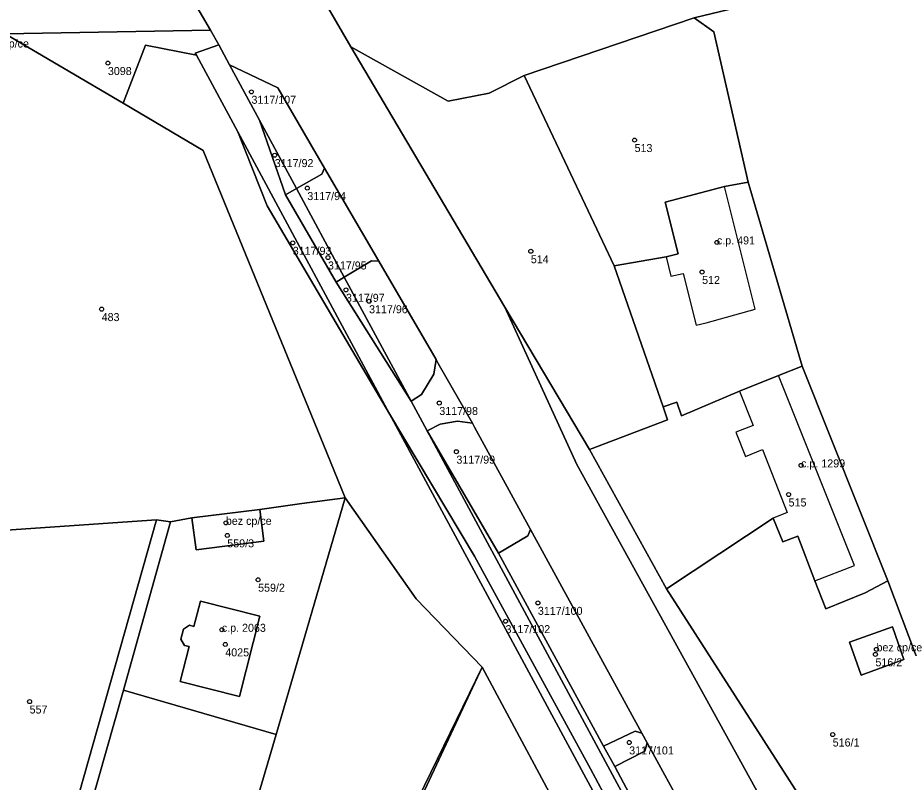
# Model space of a CAD drawing. Extents: x -878211 to -870363, y -1058464 to -1052522.
# Drawn here: x -874178.2 to -874067.3, y -1056521.1 to -1056425.6 of the extents above; entities that cross this region are included whole.
import ezdxf

# ---------------------------------------------------------------- set-up
doc = ezdxf.new("R2010")
doc.units = 0
for name, color, linetype in [('Definiční body', 7, 'Continuous'), ('Polygon budovy', 7, 'Continuous'), ('Polygon parcely', 7, 'Continuous')]:
    doc.layers.add(name, color=color, linetype=linetype)

msp = doc.modelspace()

# ---------------------------------------------------------------- linework, layer by layer
at = {"layer": 'Definiční body'}
for centre in [(-874166.98, -1056431.25994), (-874149.04, -1056434.84994), (-874101.17, -1056440.87994), (-874146.13, -1056442.75994), (-874142.06, -1056446.87994), (-874143.88, -1056453.71994), (-874090.88, -1056453.65994), (-874114.13, -1056454.76994), (-874139.48, -1056455.54994), (-874092.73, -1056457.35994), (-874137.23, -1056459.58994), (-874167.76, -1056461.99994), (-874134.34, -1056461.01994), (-874125.57, -1056473.72994), (-874123.43, -1056479.80994), (-874080.36, -1056481.51994), (-874081.92, -1056485.15994), (-874152.24, -1056488.69994), (-874152.06, -1056490.26994), (-874148.21, -1056495.80994), (-874113.25, -1056498.69994), (-874117.29, -1056500.98994), (-874152.74, -1056502.05994), (-874152.31, -1056503.88994), (-874071.07, -1056505.12994), (-874070.94, -1056504.49994), (-874176.76, -1056511.02994), (-874076.41, -1056515.14994), (-874101.84, -1056516.13994)]:
    msp.add_circle(centre, 0.25, dxfattribs=at)
at = {"layer": 'Polygon budovy'}
for points in [[(-874089.95, -1056446.66), (-874097.35, -1056448.64), (-874095.72, -1056455.08), (-874097.23, -1056455.46), (-874096.63, -1056457.89), (-874095.1, -1056457.53), (-874093.48, -1056464.01), (-874092.22, -1056463.71), (-874086.09, -1056462)], [(-874086.35, -1056476.52), (-874088.53, -1056477.37), (-874087.32, -1056480.4), (-874085.18, -1056479.53), (-874082.1, -1056487.39), (-874083.83, -1056488.11), (-874082.65, -1056491.07), (-874080.77, -1056490.34), (-874078.64, -1056495.93), (-874073.7, -1056494.04), (-874083.18, -1056470.28), (-874088.06, -1056472.24)], [(-874156.47, -1056488.08), (-874155.95, -1056492.05), (-874147.51, -1056491), (-874148.01, -1056487.01)], [(-874157.94, -1056508.51), (-874150.53, -1056510.38), (-874148, -1056500.36), (-874155.4, -1056498.48), (-874156.24, -1056501.63), (-874156.77, -1056501.5), (-874157.54, -1056501.97), (-874157.85, -1056503.23), (-874157.39, -1056504.01), (-874156.83, -1056504.14)], [(-874074.32, -1056503.61), (-874072.85, -1056507.73), (-874067.53, -1056505.77), (-874068.92, -1056501.68)]]:
    msp.add_lwpolyline(points, close=True, dxfattribs=at)
at = {"layer": 'Polygon parcely'}
for points in [[(-874187.91, -1056392.42), (-874187.93, -1056392.27), (-874192.41, -1056392.72), (-874217.28, -1056395.19), (-874225.19, -1056395.94), (-874229.19, -1056396.32), (-874228.99, -1056398.61), (-874228.45, -1056416.31), (-874210.86, -1056419.14), (-874197.06, -1056422.85), (-874179.81, -1056427.6), (-874154.17, -1056427.16), (-874163.72, -1056410.72), (-874173.61, -1056415.73), (-874176.3, -1056417.15), (-874183.73, -1056402.77), (-874181.01, -1056401.38), (-874171.09, -1056396.34), (-874175.45, -1056388.23), (-874178.92, -1056382.86), (-874179.98, -1056382.53), (-874184.44, -1056385.88), (-874184.13, -1056391.88)], [(-874103.73, -1056456.59), (-874097.23, -1056455.46), (-874095.72, -1056455.08), (-874097.35, -1056448.64), (-874089.95, -1056446.66), (-874086.97, -1056446.13), (-874091.26, -1056427.37), (-874093.72, -1056425.61), (-874114.96, -1056432.8)], [(-874162.29, -1056429), (-874155.92, -1056430.26), (-874156.06, -1056430.01), (-874153.11, -1056428.98), (-874154.17, -1056427.16), (-874179.81, -1056427.6), (-874165.08, -1056436.27)], [(-874148.01, -1056487.01), (-874142.75, -1056486.28), (-874137.32, -1056485.56), (-874139.61, -1056479.95), (-874155.08, -1056442.16), (-874165.08, -1056436.27), (-874179.81, -1056427.6), (-874179.72, -1056427.84), (-874180.47, -1056441.86), (-874181.49, -1056460.83), (-874181.07, -1056463.79), (-874180.82, -1056465.57), (-874182.09, -1056489.79), (-874160.92, -1056488.32), (-874159.16, -1056488.56), (-874156.47, -1056488.08)], [(-874097.6, -1056474.21), (-874103.73, -1056456.59), (-874114.96, -1056432.8), (-874119.33, -1056435), (-874124.47, -1056436), (-874136.62, -1056429.22), (-874117.36, -1056461.73), (-874106.82, -1056479.54), (-874097.06, -1056475.82)], [(-874148.04, -1056438.4), (-874143.43, -1056446.94), (-874140.23, -1056445.12), (-874139.9, -1056444.4), (-874145.75, -1056434.35), (-874151.78, -1056431.47)], [(-874143.43, -1056446.94), (-874148.04, -1056438.4), (-874144.78, -1056447.71)], [(-874150.75, -1056439.85), (-874147.09, -1056449.07), (-874131.77, -1056475.08)], [(-874139.9, -1056444.4), (-874140.23, -1056445.12), (-874143.43, -1056446.94), (-874137.46, -1056458), (-874134.06, -1056455.94), (-874133.13, -1056456)], [(-874097.35, -1056448.64), (-874095.72, -1056455.08), (-874097.23, -1056455.46), (-874103.73, -1056456.59), (-874097.6, -1056474.21), (-874095.88, -1056473.61), (-874095.29, -1056475.34), (-874088.06, -1056472.24), (-874083.18, -1056470.28), (-874080.24, -1056469.1), (-874086.97, -1056446.13), (-874089.95, -1056446.66)], [(-874138.46, -1056458.61), (-874137.46, -1056458), (-874143.43, -1056446.94), (-874144.78, -1056447.71)], [(-874125.98, -1056468.28), (-874133.13, -1056456), (-874134.06, -1056455.94), (-874137.46, -1056458), (-874129.09, -1056473.51), (-874127.78, -1056472.67), (-874126.26, -1056470.14)], [(-874138.46, -1056458.61), (-874129.09, -1056473.51), (-874137.46, -1056458)], [(-874097.18, -1056496.94), (-874106.82, -1056479.54), (-874117.36, -1056461.73), (-874108.38, -1056481.4), (-874084.77, -1056524.21), (-874056.05, -1056577), (-874058.74, -1056569.35), (-874070.76, -1056541.63), (-874078.23, -1056526.48)], [(-874127.07, -1056477.21), (-874125.47, -1056476.37), (-874123.28, -1056476.01), (-874121.43, -1056476.25), (-874125.69, -1056468.78), (-874125.98, -1056468.28), (-874126.26, -1056470.14), (-874127.78, -1056472.67), (-874129.09, -1056473.51)], [(-874077.27, -1056499.42), (-874072.34, -1056497.46), (-874069.52, -1056495.93), (-874080.24, -1056469.1), (-874083.18, -1056470.28), (-874088.06, -1056472.24), (-874095.29, -1056475.34), (-874095.88, -1056473.61), (-874097.6, -1056474.21), (-874097.06, -1056475.82), (-874106.82, -1056479.54), (-874097.18, -1056496.94), (-874083.83, -1056488.11), (-874082.65, -1056491.07), (-874080.77, -1056490.34), (-874078.64, -1056495.93)], [(-874131.77, -1056475.08), (-874129.83, -1056478.68), (-874071.49, -1056586.91), (-874076.38, -1056576.74), (-874087.44, -1056555.37), (-874096.5, -1056538.44), (-874106.68, -1056519.41), (-874121.15, -1056492.86)], [(-874118.15, -1056492.49), (-874114.52, -1056490.3), (-874114.17, -1056489.53), (-874121.16, -1056476.73), (-874121.43, -1056476.25), (-874123.28, -1056476.01), (-874125.47, -1056476.37), (-874127.07, -1056477.21)], [(-874085.98, -1056552.34), (-874094.7, -1056535.93), (-874103.63, -1056519.14), (-874105.05, -1056516.61), (-874118.15, -1056492.49), (-874127.07, -1056477.21), (-874074.13, -1056575.46), (-874084.3, -1056555.51)], [(-874159.16, -1056488.56), (-874165.02, -1056509.6), (-874145.95, -1056515.13), (-874137.32, -1056485.56), (-874142.75, -1056486.28), (-874148.01, -1056487.01), (-874147.51, -1056491), (-874155.95, -1056492.05), (-874156.47, -1056488.08)], [(-874149.6, -1056555.55), (-874140.8, -1056547.67), (-874143.43, -1056546.21), (-874139.77, -1056539.66), (-874137, -1056541.16), (-874120.23, -1056506.71), (-874128.46, -1056498.19), (-874137.32, -1056485.56), (-874145.95, -1056515.13), (-874151.01, -1056532.24), (-874155.61, -1056535.02), (-874159.27, -1056539.33), (-874147.66, -1056546.23), (-874151.73, -1056553.15), (-874157.54, -1056549.7), (-874150.85, -1056556.73)], [(-874148.01, -1056487.01), (-874156.47, -1056488.08), (-874155.95, -1056492.05), (-874147.51, -1056491)], [(-874190.09, -1056529.9), (-874183.71, -1056528.93), (-874183, -1056533.63), (-874173.41, -1056532.51), (-874160.92, -1056488.32), (-874182.09, -1056489.79), (-874182.44, -1056494.26), (-874189.66, -1056527.88)], [(-874069.52, -1056495.93), (-874072.34, -1056497.46), (-874077.27, -1056499.42), (-874078.64, -1056495.93), (-874080.77, -1056490.34), (-874082.65, -1056491.07), (-874083.83, -1056488.11), (-874097.18, -1056496.94), (-874078.23, -1056526.48), (-874073.61, -1056527.53), (-874058.67, -1056530.92), (-874058.03, -1056527.95), (-874059.02, -1056523.78)], [(-874105.05, -1056516.61), (-874101.11, -1056514.71), (-874100.27, -1056514.97), (-874114.17, -1056489.53), (-874114.52, -1056490.3), (-874118.15, -1056492.49)], [(-874148, -1056500.36), (-874155.4, -1056498.48), (-874156.24, -1056501.63), (-874156.77, -1056501.5), (-874157.54, -1056501.97), (-874157.85, -1056503.23), (-874157.39, -1056504.01), (-874156.83, -1056504.14), (-874157.94, -1056508.51), (-874150.53, -1056510.38)], [(-874148, -1056500.36), (-874150.53, -1056510.38), (-874157.94, -1056508.51), (-874156.83, -1056504.14), (-874157.39, -1056504.01), (-874157.85, -1056503.23), (-874157.54, -1056501.97), (-874156.77, -1056501.5), (-874156.24, -1056501.63), (-874155.4, -1056498.48)], [(-874072.85, -1056507.73), (-874074.32, -1056503.61), (-874068.92, -1056501.68), (-874067.53, -1056505.77)], [(-874072.85, -1056507.73), (-874067.53, -1056505.77), (-874068.92, -1056501.68), (-874074.32, -1056503.61)], [(-874147.92, -1056560.21), (-874141.97, -1056554.88), (-874137.24, -1056560.08), (-874131.94, -1056556.38), (-874130.5, -1056555.14), (-874108.42, -1056528.72), (-874120.23, -1056506.71), (-874136.47, -1056541.45), (-874140.03, -1056547.79), (-874139.93, -1056547.88), (-874136.31, -1056541.55), (-874132.68, -1056543.79), (-874136.83, -1056550.83), (-874139.61, -1056548.17), (-874149.43, -1056555.67), (-874150.85, -1056556.73), (-874150.26, -1056557.43)], [(-874120.23, -1056506.71), (-874137, -1056541.16), (-874136.47, -1056541.45)], [(-874169.41, -1056542.67), (-874173.44, -1056540.3), (-874169.33, -1056533.36), (-874159.27, -1056539.33), (-874155.61, -1056535.02), (-874151.01, -1056532.24), (-874145.95, -1056515.13), (-874165.02, -1056509.6), (-874171.43, -1056532.16), (-874174.84, -1056544.14)], [(-874099.61, -1056516.18), (-874100.27, -1056514.97), (-874101.11, -1056514.71), (-874105.05, -1056516.61), (-874103.63, -1056519.14), (-874099.9, -1056517.21)], [(-874085.98, -1056552.34), (-874082.16, -1056550.32), (-874081.18, -1056550.68), (-874094.74, -1056525.1), (-874099.61, -1056516.18), (-874099.9, -1056517.21), (-874103.63, -1056519.14), (-874094.7, -1056535.93)]]:
    msp.add_lwpolyline(points, close=True, dxfattribs=at)
for points in [[(-873895.24, -1056850.14), (-873908.21, -1056824.62), (-873940.24, -1056755.07), (-873950.29, -1056741.89), (-873967.11, -1056720.96), (-873969.65, -1056722.8), (-873973.32, -1056718.02), (-874002.89, -1056678.66), (-874011.69, -1056666.89), (-874009.12, -1056664.87), (-874011.97, -1056661.51), (-874024.62, -1056638.91), (-874042.06, -1056605.74), (-874043.43, -1056601.67), (-874041.78, -1056601.01), (-874055.1, -1056577.75), (-874058.74, -1056569.35), (-874056.05, -1056577), (-874084.77, -1056524.21), (-874108.38, -1056481.4), (-874117.36, -1056461.73), (-874136.62, -1056429.22), (-874154.14, -1056399.02)], [(-874154.14, -1056399.02), (-874136.62, -1056429.22), (-874124.47, -1056436), (-874119.33, -1056435), (-874114.96, -1056432.8), (-874093.72, -1056425.61), (-874089.4, -1056424.57)], [(-874163.72, -1056410.72), (-874154.17, -1056427.16), (-874153.11, -1056428.98), (-874151.78, -1056431.47), (-874145.75, -1056434.35), (-874139.9, -1056444.4), (-874133.13, -1056456), (-874125.98, -1056468.28), (-874125.69, -1056468.78), (-874121.43, -1056476.25), (-874121.16, -1056476.73), (-874114.17, -1056489.53), (-874100.27, -1056514.97), (-874099.61, -1056516.18), (-874094.74, -1056525.1), (-874081.18, -1056550.68), (-874080.26, -1056552.41), (-874073.59, -1056565.01), (-874068.6, -1056574.52), (-874060.08, -1056590.74)], [(-874089.4, -1056424.57), (-874093.72, -1056425.61), (-874091.26, -1056427.37), (-874086.97, -1056446.13), (-874080.24, -1056469.1), (-874069.52, -1056495.93), (-874059.02, -1056523.78), (-874058.03, -1056527.95), (-874058.67, -1056530.92), (-874056.84, -1056534.05), (-874035.88, -1056579.88), (-874041.25, -1056593.06), (-874019.42, -1056638.08), (-874011.45, -1056652.11), (-873975.84, -1056699.09), (-873943.35, -1056736.97), (-873935.01, -1056752.39), (-873930.75, -1056761.9), (-873920.07, -1056788.11), (-873906.75, -1056817.03), (-873873.73, -1056840.56), (-873864.45, -1056848.53)], [(-874071.49, -1056586.91), (-874129.83, -1056478.68), (-874131.77, -1056475.08), (-874147.09, -1056449.07), (-874150.75, -1056439.85), (-874155.92, -1056430.26), (-874162.29, -1056429), (-874165.08, -1056436.27), (-874155.08, -1056442.16), (-874139.61, -1056479.95), (-874137.32, -1056485.56), (-874128.46, -1056498.19), (-874120.23, -1056506.71), (-874108.42, -1056528.72)], [(-874067.25, -1056633.06), (-874067.63, -1056611.01), (-874067.96, -1056591.56), (-874068.07, -1056586.7), (-874074.13, -1056575.46), (-874127.07, -1056477.21), (-874129.09, -1056473.51), (-874138.46, -1056458.61), (-874144.78, -1056447.71), (-874148.04, -1056438.4), (-874151.78, -1056431.47), (-874153.11, -1056428.98), (-874156.06, -1056430.01), (-874155.92, -1056430.26), (-874150.75, -1056439.85), (-874131.77, -1056475.08), (-874121.15, -1056492.86), (-874106.68, -1056519.41), (-874096.5, -1056538.44), (-874087.44, -1056555.37), (-874076.38, -1056576.74), (-874071.49, -1056586.91)], [(-874171.43, -1056532.16), (-874165.02, -1056509.6), (-874159.16, -1056488.56), (-874160.92, -1056488.32), (-874173.41, -1056532.51)]]:
    msp.add_lwpolyline(points, dxfattribs=at)

# ---------------------------------------------------------------- texts
at = {"layer": 'Definiční body'}
for s, p in [('bez cp/ce', (-874182.57, -1056429.31)), ('3098', (-874166.98, -1056432.749)), ('3117/107', (-874149.04, -1056436.339)), ('513', (-874101.17, -1056442.369)), ('3117/92', (-874146.13, -1056444.249)), ('3117/94', (-874142.06, -1056448.369)), ('c.p. 491', (-874090.88, -1056453.909)), ('3117/93', (-874143.88, -1056455.209)), ('3117/95', (-874139.48, -1056457.039)), ('514', (-874114.13, -1056456.259)), ('512', (-874092.73, -1056458.849)), ('3117/97', (-874137.23, -1056461.079)), ('3117/96', (-874134.34, -1056462.509)), ('483', (-874167.76, -1056463.489)), ('3117/98', (-874125.57, -1056475.219)), ('3117/99', (-874123.43, -1056481.299)), ('c.p. 1299', (-874080.36, -1056481.77)), ('515', (-874081.92, -1056486.649)), ('bez cp/ce', (-874152.24, -1056488.95)), ('559/3', (-874152.06, -1056491.759)), ('559/2', (-874148.21, -1056497.299)), ('3117/100', (-874113.25, -1056500.189)), ('c.p. 2063', (-874152.74, -1056502.31)), ('3117/102', (-874117.29, -1056502.479)), ('bez cp/ce', (-874070.94, -1056504.75)), ('4025', (-874152.31, -1056505.379)), ('516/2', (-874071.07, -1056506.619)), ('557', (-874176.76, -1056512.519)), ('516/1', (-874076.41, -1056516.639)), ('3117/101', (-874101.84, -1056517.629))]:
    msp.add_text(s, height=0.999996, dxfattribs=at).set_placement(p)

doc.saveas('drawing.dxf')
